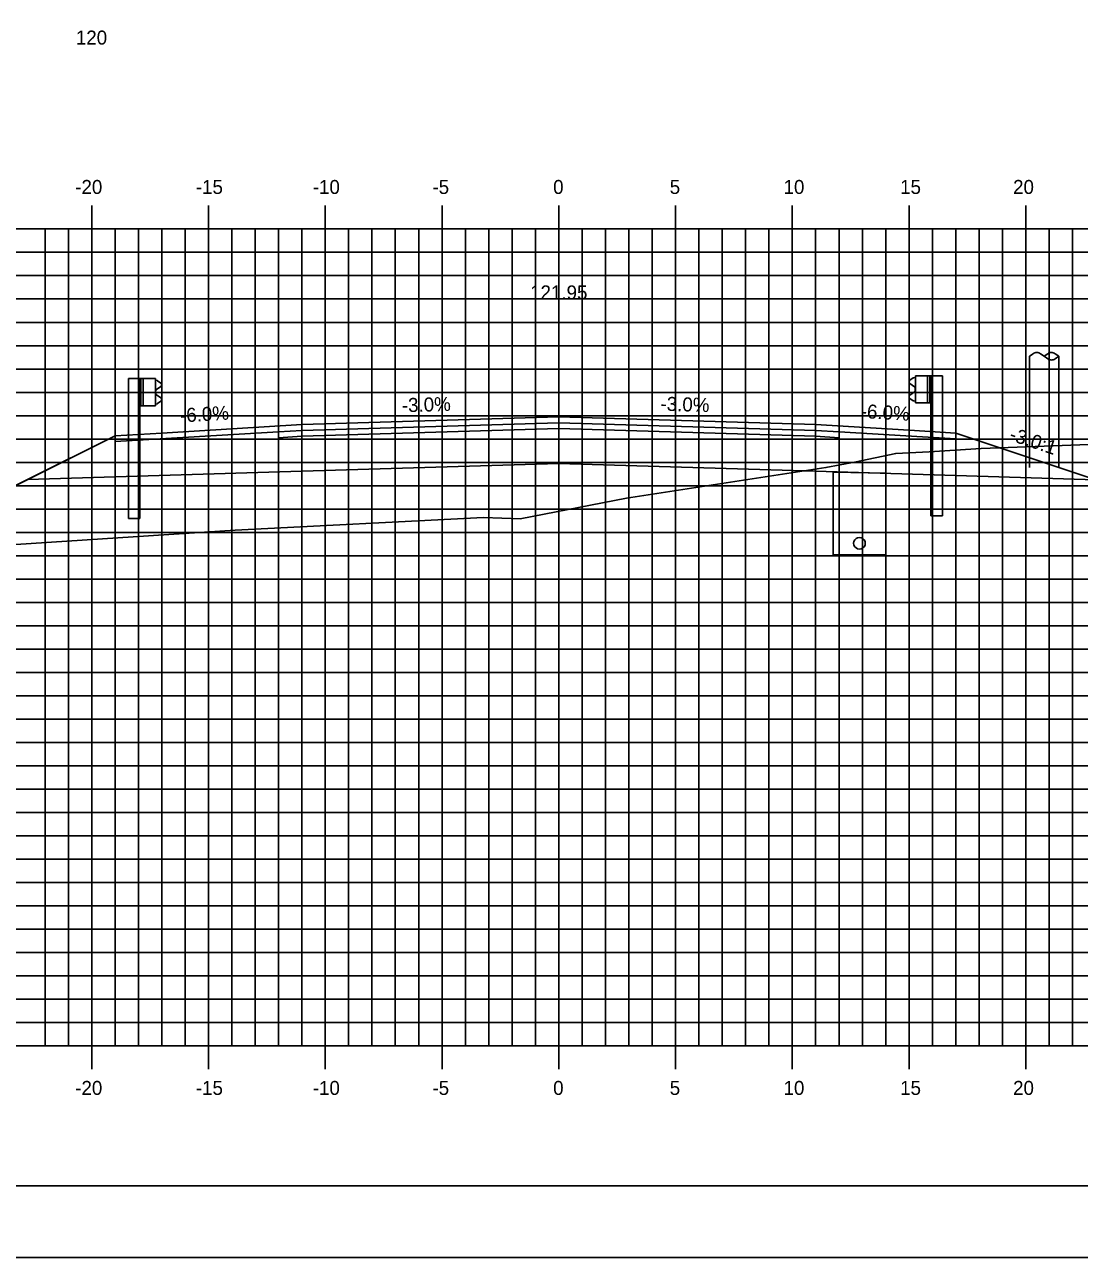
# Model space of a CAD drawing. Extents: x 850598 to 870284, y 366541 to 366651.
# Drawn here: x 857502.5 to 857547.6, y 366541.2 to 366594 of the extents above; entities that cross this region are included whole.
import ezdxf

# ---------------------------------------------------------------- set-up
doc = ezdxf.new("R2010")
doc.units = 0
for name, color, linetype in [('ANNOTATION', 7, 'Continuous'), ('BORDER', 7, 'Continuous'), ('D_Drainage_Underdrain', 7, 'Continuous'), ('D_Drainage_Underdrain_06in', 7, 'Continuous'), ('D_Guardrail_Beam_Lt', 7, 'Continuous'), ('D_Guardrail_Beam_Rt', 7, 'Continuous'), ('D_Roadway_Centerline', 7, 'Continuous'), ('D_Roadway_Centerline_Text', 7, 'Continuous'), ('D_Roadway_Edge_Shoulder', 7, 'Continuous'), ('D_Roadway_Edge_TW', 7, 'Continuous'), ('D_Roadway_Pavement', 7, 'Continuous'), ('D_Roadway_SlopeLines', 7, 'Continuous'), ('D_Roadway_SubGrade', 7, 'Continuous'), ('D_Utilities_Pole_Joint', 7, 'Continuous'), ('H_V ANNOTATION', 7, 'Continuous'), ('MAJOR', 7, 'Continuous'), ('MINOR', 7, 'Continuous'), ('PLOT BOUNDARY', 7, 'Continuous'), ('S_Roadway_Centerline', 7, 'Continuous')]:
    doc.layers.add(name, color=color, linetype=linetype)

msp = doc.modelspace()

# ---------------------------------------------------------------- linework, layer by layer
at = {"layer": 'BORDER'}
msp.add_line((857480.35, 366544.225), (857640.35, 366544.225), dxfattribs=at)
at = {"layer": 'D_Drainage_Underdrain'}
msp.add_lwpolyline([(857539.35, 366574.761), (857539.35, 366571.26), (857537.1, 366571.26), (857537.1, 366574.806)], close=True, dxfattribs=at)
at = {"layer": 'D_Drainage_Underdrain_06in'}
msp.add_lwpolyline([(857538.225, 366572.01), (857538.148, 366571.998), (857538.078, 366571.963), (857538.023, 366571.907), (857537.987, 366571.838), (857537.975, 366571.76), (857537.987, 366571.683), (857538.023, 366571.613), (857538.078, 366571.558), (857538.148, 366571.523), (857538.225, 366571.51), (857538.302, 366571.523), (857538.372, 366571.558), (857538.427, 366571.613), (857538.463, 366571.683), (857538.475, 366571.76), (857538.463, 366571.838), (857538.427, 366571.907), (857538.372, 366571.963), (857538.302, 366571.998)], close=True, dxfattribs=at)
at = {"layer": 'D_Guardrail_Beam_Lt'}
for p, q in [((857506.921, 366578.816), (857506.921, 366572.816)), ((857507.392, 366578.816), (857506.921, 366578.816)), ((857508.079, 366578.816), (857507.392, 366578.816)), ((857507.392, 366578.816), (857507.392, 366577.65)), ((857507.454, 366578.816), (857507.454, 366577.65)), ((857507.558, 366578.816), (857507.558, 366577.65)), ((857508.079, 366577.65), (857508.079, 366578.816)), ((857508.079, 366578.742), (857508.152, 366578.729)), ((857508.169, 366578.722), (857508.312, 366578.622)), ((857508.083, 366578.278), (857508.083, 366578.187)), ((857508.312, 366578.479), (857508.117, 366578.343)), ((857507.392, 366577.65), (857508.079, 366577.65)), ((857507.412, 366572.816), (857507.412, 366577.65)), ((857508.152, 366577.737), (857508.079, 366577.724)), ((857508.117, 366578.123), (857508.312, 366577.987)), ((857508.312, 366577.844), (857508.169, 366577.744)), ((857507.412, 366572.816), (857506.921, 366572.816))]:
    msp.add_line(p, q, dxfattribs=at)
for centre, major_axis, start_param, end_param in [((857508.145, 366578.688), (0.0417, 0), 0.959931, 1.396263), ((857508.162, 366578.278), (-0.0789, 0), 5.323254, 6.283185), ((857508.162, 366578.187), (-0.0789, 0), 6.283185, 7.243116), ((857508.262, 366578.55), (0.0877, 0), 5.323254, 7.243116), ((857508.145, 366577.778), (0.0417, 0), 4.886922, 5.323254), ((857508.262, 366577.915), (0.0877, 0), 5.323254, 7.243116)]:
    msp.add_ellipse(centre, major_axis=major_axis, ratio=0.995501, start_param=start_param, end_param=end_param, dxfattribs=at)
at = {"layer": 'D_Guardrail_Beam_Rt'}
for p, q in [((857540.531, 366578.842), (857540.387, 366578.742)), ((857540.621, 366578.862), (857540.547, 366578.849)), ((857540.621, 366578.936), (857541.308, 366578.936)), ((857540.621, 366577.77), (857540.621, 366578.936)), ((857541.141, 366578.936), (857541.141, 366577.77)), ((857541.246, 366578.936), (857541.246, 366577.77)), ((857541.308, 366578.936), (857541.779, 366578.936)), ((857541.308, 366578.936), (857541.308, 366577.77)), ((857541.779, 366578.936), (857541.779, 366572.936)), ((857540.387, 366578.599), (857540.583, 366578.463)), ((857540.583, 366578.243), (857540.387, 366578.107)), ((857540.616, 366578.398), (857540.616, 366578.307)), ((857540.387, 366577.964), (857540.531, 366577.864)), ((857540.547, 366577.857), (857540.621, 366577.844)), ((857541.308, 366577.77), (857540.621, 366577.77)), ((857541.287, 366572.936), (857541.287, 366577.77)), ((857541.287, 366572.936), (857541.779, 366572.936))]:
    msp.add_line(p, q, dxfattribs=at)
for centre, major_axis, start_param, end_param in [((857540.438, 366578.67), (-0.0877, 0), 5.323254, 7.243116), ((857540.555, 366578.808), (-0.0417, 0), 4.886922, 5.323254), ((857540.537, 366578.398), (0.0789, 0), 0, 0.959931), ((857540.537, 366578.307), (0.0789, 0), 5.323254, 6.283185), ((857540.438, 366578.035), (-0.0877, 0), 5.323254, 7.243116), ((857540.555, 366577.898), (-0.0417, 0), 0.959931, 1.396263)]:
    msp.add_ellipse(centre, major_axis=major_axis, ratio=0.995501, start_param=start_param, end_param=end_param, dxfattribs=at)
at = {"layer": 'D_Roadway_Centerline'}
msp.add_lwpolyline([(857493.745, 366570.06), (857496.35, 366571.363), (857502.605, 366574.491), (857506.35, 366576.363), (857508.35, 366576.483), (857514.35, 366576.843), (857525.35, 366577.173), (857536.35, 366576.843), (857540.35, 366576.603), (857542.35, 366576.483), (857548.35, 366574.483), (857604.246, 366563.225), (857624.175, 366559.212), (857625.35, 366558.975)], dxfattribs=at)
at = {"layer": 'D_Roadway_Edge_Shoulder'}
for points in [[(857514.35, 366576.843), (857508.35, 366576.483), (857508.35, 366576.483), (857506.35, 366576.363), (857506.35, 366576.113), (857513.35, 366576.533), (857514.35, 366576.593)], [(857536.35, 366576.843), (857540.35, 366576.603), (857540.35, 366576.603), (857542.35, 366576.483), (857542.35, 366576.233), (857537.35, 366576.533), (857536.35, 366576.593)]]:
    msp.add_lwpolyline(points, close=True, dxfattribs=at)
at = {"layer": 'D_Roadway_Edge_TW'}
msp.add_lwpolyline([(857514.35, 366576.593), (857514.35, 366576.843), (857525.35, 366577.173), (857536.35, 366576.843), (857536.35, 366576.593), (857525.35, 366576.923)], close=True, dxfattribs=at)
at = {"layer": 'D_Roadway_Pavement'}
for points in [[(857514.35, 366576.593), (857513.35, 366576.533), (857513.35, 366576.283), (857514.35, 366576.343)], [(857514.35, 366576.343), (857514.35, 366576.593), (857525.35, 366576.923), (857536.35, 366576.593), (857536.35, 366576.343), (857525.35, 366576.673)], [(857536.35, 366576.593), (857537.35, 366576.533), (857537.35, 366576.283), (857536.35, 366576.343)]]:
    msp.add_lwpolyline(points, close=True, dxfattribs=at)
at = {"layer": 'D_Roadway_SlopeLines'}
msp.add_lwpolyline([(857506.35, 366576.363), (857496.35, 366571.363)], dxfattribs=at)
at = {"layer": 'D_Roadway_SubGrade'}
for points in [[(857514.35, 366574.843), (857514.35, 366576.343), (857525.35, 366576.673), (857536.35, 366576.343), (857536.35, 366574.843), (857525.35, 366575.173)], [(857514.35, 366576.343), (857513.35, 366576.283), (857513.35, 366576.533), (857506.35, 366576.113), (857506.35, 366576.363), (857502.605, 366574.491), (857514.35, 366574.843)], [(857536.35, 366576.343), (857537.35, 366576.283), (857537.35, 366576.533), (857542.35, 366576.233), (857542.35, 366576.483), (857548.35, 366574.483), (857536.35, 366574.843)]]:
    msp.add_lwpolyline(points, close=True, dxfattribs=at)
msp.add_lwpolyline([(857506.35, 366576.363), (857502.605, 366574.491), (857506.35, 366576.363)], dxfattribs=at)
at = {"layer": 'D_Utilities_Pole_Joint'}
for p, q in [((857545.506, 366579.77), (857545.662, 366579.88)), ((857545.506, 366575.012), (857545.506, 366579.77)), ((857545.974, 366579.88), (857546.13, 366579.77)), ((857546.287, 366579.88), (857546.13, 366579.77)), ((857546.13, 366579.77), (857546.287, 366579.659)), ((857546.756, 366579.77), (857546.6, 366579.88)), ((857546.6, 366579.659), (857546.756, 366579.77)), ((857546.756, 366575.012), (857546.756, 366579.77))]:
    msp.add_line(p, q, dxfattribs=at)
for centre, start, end in [((857545.818, 366579.659), 90, 125.2644), ((857545.818, 366579.659), 54.7356, 90), ((857546.443, 366579.659), 90, 125.2644), ((857546.443, 366579.659), 54.7356, 90), ((857546.443, 366579.88), 234.7356, 270), ((857546.443, 366579.88), 270, 305.2644)]:
    msp.add_arc(centre, 0.271, start, end, dxfattribs=at)
at = {"layer": 'MAJOR'}
for p, q in [((857505.35, 366586.227), (857505.35, 366585.225)), ((857505.35, 366586.227), (857505.35, 366585.225)), ((857510.35, 366586.227), (857510.35, 366585.225)), ((857510.35, 366586.227), (857510.35, 366585.225)), ((857515.35, 366586.227), (857515.35, 366585.225)), ((857515.35, 366586.227), (857515.35, 366585.225)), ((857520.35, 366586.227), (857520.35, 366585.225)), ((857520.35, 366586.227), (857520.35, 366585.225)), ((857525.35, 366586.227), (857525.35, 366585.225)), ((857525.35, 366586.227), (857525.35, 366585.225)), ((857530.35, 366586.227), (857530.35, 366585.225)), ((857530.35, 366586.227), (857530.35, 366585.225)), ((857535.35, 366586.227), (857535.35, 366585.225)), ((857535.35, 366586.227), (857535.35, 366585.225)), ((857540.35, 366586.227), (857540.35, 366585.225)), ((857540.35, 366586.227), (857540.35, 366585.225)), ((857545.35, 366586.227), (857545.35, 366585.225)), ((857545.35, 366586.227), (857545.35, 366585.225)), ((857485.35, 366585.225), (857625.35, 366585.225)), ((857485.35, 366585.225), (857625.35, 366585.225)), ((857485.35, 366585.225), (857625.35, 366585.225)), ((857485.35, 366585.225), (857625.35, 366585.225)), ((857505.35, 366550.225), (857505.35, 366585.225)), ((857505.35, 366550.225), (857505.35, 366585.225)), ((857510.35, 366550.225), (857510.35, 366585.225)), ((857510.35, 366550.225), (857510.35, 366585.225)), ((857515.35, 366550.225), (857515.35, 366585.225)), ((857515.35, 366550.225), (857515.35, 366585.225)), ((857520.35, 366550.225), (857520.35, 366585.225)), ((857520.35, 366550.225), (857520.35, 366585.225)), ((857525.35, 366550.225), (857525.35, 366585.225)), ((857525.35, 366550.225), (857525.35, 366585.225)), ((857530.35, 366550.225), (857530.35, 366585.225)), ((857530.35, 366550.225), (857530.35, 366585.225)), ((857535.35, 366550.225), (857535.35, 366585.225)), ((857535.35, 366550.225), (857535.35, 366585.225)), ((857540.35, 366550.225), (857540.35, 366585.225)), ((857540.35, 366550.225), (857540.35, 366585.225)), ((857545.35, 366550.225), (857545.35, 366585.225)), ((857545.35, 366550.225), (857545.35, 366585.225)), ((857485.35, 366580.225), (857625.35, 366580.225)), ((857485.35, 366580.225), (857625.35, 366580.225)), ((857485.35, 366575.225), (857625.35, 366575.225)), ((857485.35, 366575.225), (857625.35, 366575.225)), ((857485.35, 366570.225), (857625.35, 366570.225)), ((857485.35, 366570.225), (857625.35, 366570.225)), ((857485.35, 366565.225), (857625.35, 366565.225)), ((857485.35, 366565.225), (857625.35, 366565.225)), ((857485.35, 366560.225), (857625.35, 366560.225)), ((857485.35, 366560.225), (857625.35, 366560.225)), ((857485.35, 366555.225), (857625.35, 366555.225)), ((857485.35, 366555.225), (857625.35, 366555.225)), ((857485.35, 366550.225), (857625.35, 366550.225)), ((857485.35, 366550.225), (857625.35, 366550.225)), ((857485.35, 366550.225), (857625.35, 366550.225)), ((857485.35, 366550.225), (857625.35, 366550.225)), ((857505.35, 366549.223), (857505.35, 366550.225)), ((857505.35, 366549.223), (857505.35, 366550.225)), ((857510.35, 366549.223), (857510.35, 366550.225)), ((857510.35, 366549.223), (857510.35, 366550.225)), ((857515.35, 366549.223), (857515.35, 366550.225)), ((857515.35, 366549.223), (857515.35, 366550.225)), ((857520.35, 366549.223), (857520.35, 366550.225)), ((857520.35, 366549.223), (857520.35, 366550.225)), ((857525.35, 366549.223), (857525.35, 366550.225)), ((857525.35, 366549.223), (857525.35, 366550.225)), ((857530.35, 366549.223), (857530.35, 366550.225)), ((857530.35, 366549.223), (857530.35, 366550.225)), ((857535.35, 366549.223), (857535.35, 366550.225)), ((857535.35, 366549.223), (857535.35, 366550.225)), ((857540.35, 366549.223), (857540.35, 366550.225)), ((857540.35, 366549.223), (857540.35, 366550.225)), ((857545.35, 366549.223), (857545.35, 366550.225)), ((857545.35, 366549.223), (857545.35, 366550.225))]:
    msp.add_line(p, q, dxfattribs=at)
at = {"layer": 'MINOR'}
for p, q in [((857503.35, 366550.225), (857503.35, 366585.225)), ((857503.35, 366550.225), (857503.35, 366585.225)), ((857504.35, 366550.225), (857504.35, 366585.225)), ((857504.35, 366550.225), (857504.35, 366585.225)), ((857506.35, 366550.225), (857506.35, 366585.225)), ((857506.35, 366550.225), (857506.35, 366585.225)), ((857507.35, 366550.225), (857507.35, 366585.225)), ((857507.35, 366550.225), (857507.35, 366585.225)), ((857508.35, 366550.225), (857508.35, 366585.225)), ((857508.35, 366550.225), (857508.35, 366585.225)), ((857509.35, 366550.225), (857509.35, 366585.225)), ((857509.35, 366550.225), (857509.35, 366585.225)), ((857511.35, 366550.225), (857511.35, 366585.225)), ((857511.35, 366550.225), (857511.35, 366585.225)), ((857512.35, 366550.225), (857512.35, 366585.225)), ((857512.35, 366550.225), (857512.35, 366585.225)), ((857513.35, 366550.225), (857513.35, 366585.225)), ((857513.35, 366550.225), (857513.35, 366585.225)), ((857514.35, 366550.225), (857514.35, 366585.225)), ((857514.35, 366550.225), (857514.35, 366585.225)), ((857516.35, 366550.225), (857516.35, 366585.225)), ((857516.35, 366550.225), (857516.35, 366585.225)), ((857517.35, 366550.225), (857517.35, 366585.225)), ((857517.35, 366550.225), (857517.35, 366585.225)), ((857518.35, 366550.225), (857518.35, 366585.225)), ((857518.35, 366550.225), (857518.35, 366585.225)), ((857519.35, 366550.225), (857519.35, 366585.225)), ((857519.35, 366550.225), (857519.35, 366585.225)), ((857521.35, 366550.225), (857521.35, 366585.225)), ((857521.35, 366550.225), (857521.35, 366585.225)), ((857522.35, 366550.225), (857522.35, 366585.225)), ((857522.35, 366550.225), (857522.35, 366585.225)), ((857523.35, 366550.225), (857523.35, 366585.225)), ((857523.35, 366550.225), (857523.35, 366585.225)), ((857524.35, 366550.225), (857524.35, 366585.225)), ((857524.35, 366550.225), (857524.35, 366585.225)), ((857526.35, 366550.225), (857526.35, 366585.225)), ((857526.35, 366550.225), (857526.35, 366585.225)), ((857527.35, 366550.225), (857527.35, 366585.225)), ((857527.35, 366550.225), (857527.35, 366585.225)), ((857528.35, 366550.225), (857528.35, 366585.225)), ((857528.35, 366550.225), (857528.35, 366585.225)), ((857529.35, 366550.225), (857529.35, 366585.225)), ((857529.35, 366550.225), (857529.35, 366585.225)), ((857531.35, 366550.225), (857531.35, 366585.225)), ((857531.35, 366550.225), (857531.35, 366585.225)), ((857532.35, 366550.225), (857532.35, 366585.225)), ((857532.35, 366550.225), (857532.35, 366585.225)), ((857533.35, 366550.225), (857533.35, 366585.225)), ((857533.35, 366550.225), (857533.35, 366585.225)), ((857534.35, 366550.225), (857534.35, 366585.225)), ((857534.35, 366550.225), (857534.35, 366585.225)), ((857536.35, 366550.225), (857536.35, 366585.225)), ((857536.35, 366550.225), (857536.35, 366585.225)), ((857537.35, 366550.225), (857537.35, 366585.225)), ((857537.35, 366550.225), (857537.35, 366585.225)), ((857538.35, 366550.225), (857538.35, 366585.225)), ((857538.35, 366550.225), (857538.35, 366585.225)), ((857539.35, 366550.225), (857539.35, 366585.225)), ((857539.35, 366550.225), (857539.35, 366585.225)), ((857541.35, 366550.225), (857541.35, 366585.225)), ((857541.35, 366550.225), (857541.35, 366585.225)), ((857542.35, 366550.225), (857542.35, 366585.225)), ((857542.35, 366550.225), (857542.35, 366585.225)), ((857543.35, 366550.225), (857543.35, 366585.225)), ((857543.35, 366550.225), (857543.35, 366585.225)), ((857544.35, 366550.225), (857544.35, 366585.225)), ((857544.35, 366550.225), (857544.35, 366585.225)), ((857546.35, 366550.225), (857546.35, 366585.225)), ((857546.35, 366550.225), (857546.35, 366585.225)), ((857547.35, 366550.225), (857547.35, 366585.225)), ((857547.35, 366550.225), (857547.35, 366585.225)), ((857485.35, 366584.225), (857625.35, 366584.225)), ((857485.35, 366584.225), (857625.35, 366584.225)), ((857485.35, 366583.225), (857625.35, 366583.225)), ((857485.35, 366583.225), (857625.35, 366583.225)), ((857485.35, 366582.225), (857625.35, 366582.225)), ((857485.35, 366582.225), (857625.35, 366582.225)), ((857485.35, 366581.225), (857625.35, 366581.225)), ((857485.35, 366581.225), (857625.35, 366581.225)), ((857485.35, 366579.225), (857625.35, 366579.225)), ((857485.35, 366579.225), (857625.35, 366579.225)), ((857485.35, 366578.225), (857625.35, 366578.225)), ((857485.35, 366578.225), (857625.35, 366578.225)), ((857485.35, 366577.225), (857625.35, 366577.225)), ((857485.35, 366577.225), (857625.35, 366577.225)), ((857485.35, 366576.225), (857625.35, 366576.225)), ((857485.35, 366576.225), (857625.35, 366576.225)), ((857485.35, 366574.225), (857625.35, 366574.225)), ((857485.35, 366574.225), (857625.35, 366574.225)), ((857485.35, 366573.225), (857625.35, 366573.225)), ((857485.35, 366573.225), (857625.35, 366573.225)), ((857485.35, 366572.225), (857625.35, 366572.225)), ((857485.35, 366572.225), (857625.35, 366572.225)), ((857485.35, 366571.225), (857625.35, 366571.225)), ((857485.35, 366571.225), (857625.35, 366571.225)), ((857485.35, 366569.225), (857625.35, 366569.225)), ((857485.35, 366569.225), (857625.35, 366569.225)), ((857485.35, 366568.225), (857625.35, 366568.225)), ((857485.35, 366568.225), (857625.35, 366568.225)), ((857485.35, 366567.225), (857625.35, 366567.225)), ((857485.35, 366567.225), (857625.35, 366567.225)), ((857485.35, 366566.225), (857625.35, 366566.225)), ((857485.35, 366566.225), (857625.35, 366566.225)), ((857485.35, 366564.225), (857625.35, 366564.225)), ((857485.35, 366564.225), (857625.35, 366564.225)), ((857485.35, 366563.225), (857625.35, 366563.225)), ((857485.35, 366563.225), (857625.35, 366563.225)), ((857485.35, 366562.225), (857625.35, 366562.225)), ((857485.35, 366562.225), (857625.35, 366562.225)), ((857485.35, 366561.225), (857625.35, 366561.225)), ((857485.35, 366561.225), (857625.35, 366561.225)), ((857485.35, 366559.225), (857625.35, 366559.225)), ((857485.35, 366559.225), (857625.35, 366559.225)), ((857485.35, 366558.225), (857625.35, 366558.225)), ((857485.35, 366558.225), (857625.35, 366558.225)), ((857485.35, 366557.225), (857625.35, 366557.225)), ((857485.35, 366557.225), (857625.35, 366557.225)), ((857485.35, 366556.225), (857625.35, 366556.225)), ((857485.35, 366556.225), (857625.35, 366556.225)), ((857485.35, 366554.225), (857625.35, 366554.225)), ((857485.35, 366554.225), (857625.35, 366554.225)), ((857485.35, 366553.225), (857625.35, 366553.225)), ((857485.35, 366553.225), (857625.35, 366553.225)), ((857485.35, 366552.225), (857625.35, 366552.225)), ((857485.35, 366552.225), (857625.35, 366552.225)), ((857485.35, 366551.225), (857625.35, 366551.225)), ((857485.35, 366551.225), (857625.35, 366551.225))]:
    msp.add_line(p, q, dxfattribs=at)
at = {"layer": 'PLOT BOUNDARY'}
msp.add_lwpolyline([(857472.257, 366541.166), (857642.257, 366541.166), (857642.257, 366651.166), (857472.257, 366651.166)], close=True, dxfattribs=at)
at = {"layer": 'S_Roadway_Centerline'}
msp.add_lwpolyline([(857485.35, 366568.408), (857502.098, 366571.704), (857511.496, 366572.325), (857522.123, 366572.865), (857523.689, 366572.801), (857528.252, 366573.688), (857536.79, 366575), (857538.018, 366575.239), (857539.782, 366575.612), (857541.209, 366575.683), (857543.437, 366575.823), (857550.739, 366576.086)], dxfattribs=at)

# ---------------------------------------------------------------- texts
at = {"layer": 'ANNOTATION'}
for s, rotation, p in [('-6.0%', 3.4336, (857509.147, 366576.933)), ('-3.0%', 1.7184, (857518.638, 366577.372)), ('-3.0%', 358.2816, (857529.698, 366577.443)), ('-6.0%', 356.5664, (857538.267, 366577.13)), ('-3.0:1', 341.5651, (857544.604, 366576.186))]:
    msp.add_text(s, height=0.6, rotation=rotation, dxfattribs=at).set_placement(p)
at = {"layer": 'D_Roadway_Centerline'}
for s, p in [('C', (857525.345, 366577.173)), ('C', (857525.345, 366577.173)), ('L', (857525.35, 366577.166)), ('L', (857525.35, 366577.166))]:
    msp.add_text(s, height=0.0146, dxfattribs=at).set_placement(p)
at = {"layer": 'D_Roadway_Centerline_Text'}
msp.add_text('121.95', height=0.6, dxfattribs=at).set_placement((857524.122, 366582.205))
at = {"layer": 'H_V ANNOTATION'}
for s, p in [('120', (857504.67, 366593.125)), ('-20', (857504.643, 366586.725)), ('-15', (857509.807, 366586.725)), ('-10', (857514.815, 366586.725)), ('-5', (857519.94, 366586.725)), ('0', (857525.109, 366586.725)), ('5', (857530.101, 366586.725)), ('10', (857534.975, 366586.725)), ('15', (857539.967, 366586.725)), ('20', (857544.804, 366586.725)), ('-20', (857504.643, 366548.125)), ('-15', (857509.807, 366548.125)), ('-10', (857514.815, 366548.125)), ('-5', (857519.94, 366548.125)), ('0', (857525.109, 366548.125)), ('5', (857530.101, 366548.125)), ('10', (857534.975, 366548.125)), ('15', (857539.967, 366548.125)), ('20', (857544.804, 366548.125))]:
    msp.add_text(s, height=0.6, dxfattribs=at).set_placement(p)

doc.saveas('drawing.dxf')
